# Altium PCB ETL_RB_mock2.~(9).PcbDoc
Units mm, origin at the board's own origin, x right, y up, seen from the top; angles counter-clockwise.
Board outline 130.3 x 56.5 mm, 2 copper layers (Top Layer, Bottom Layer), stack 0.137 mm thick; 9 components, 186 nets, 267 pads, 123 vias.
Unrouted connection lines stored in the file: 395.
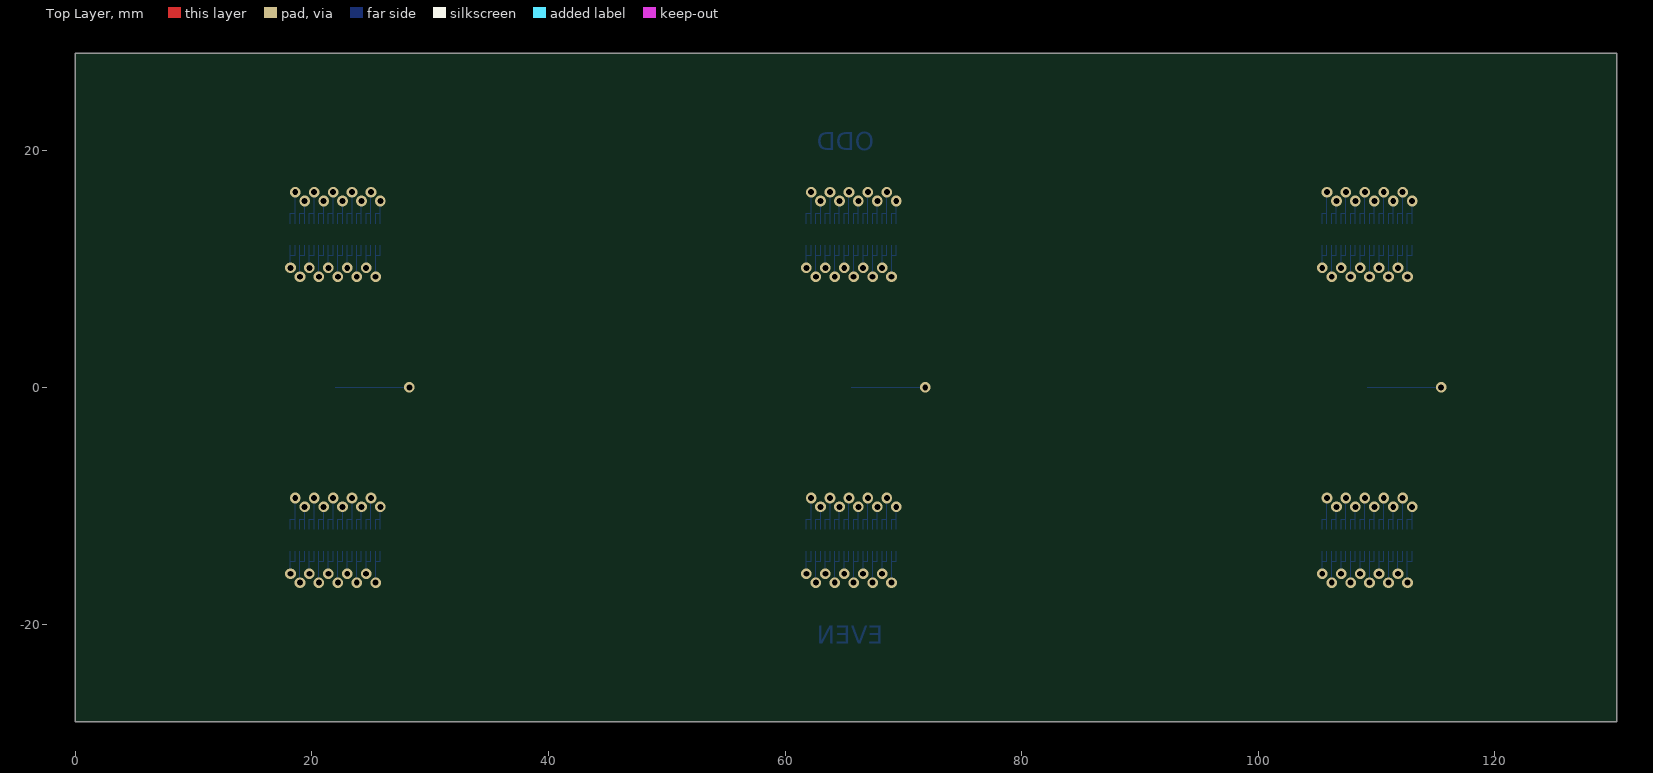
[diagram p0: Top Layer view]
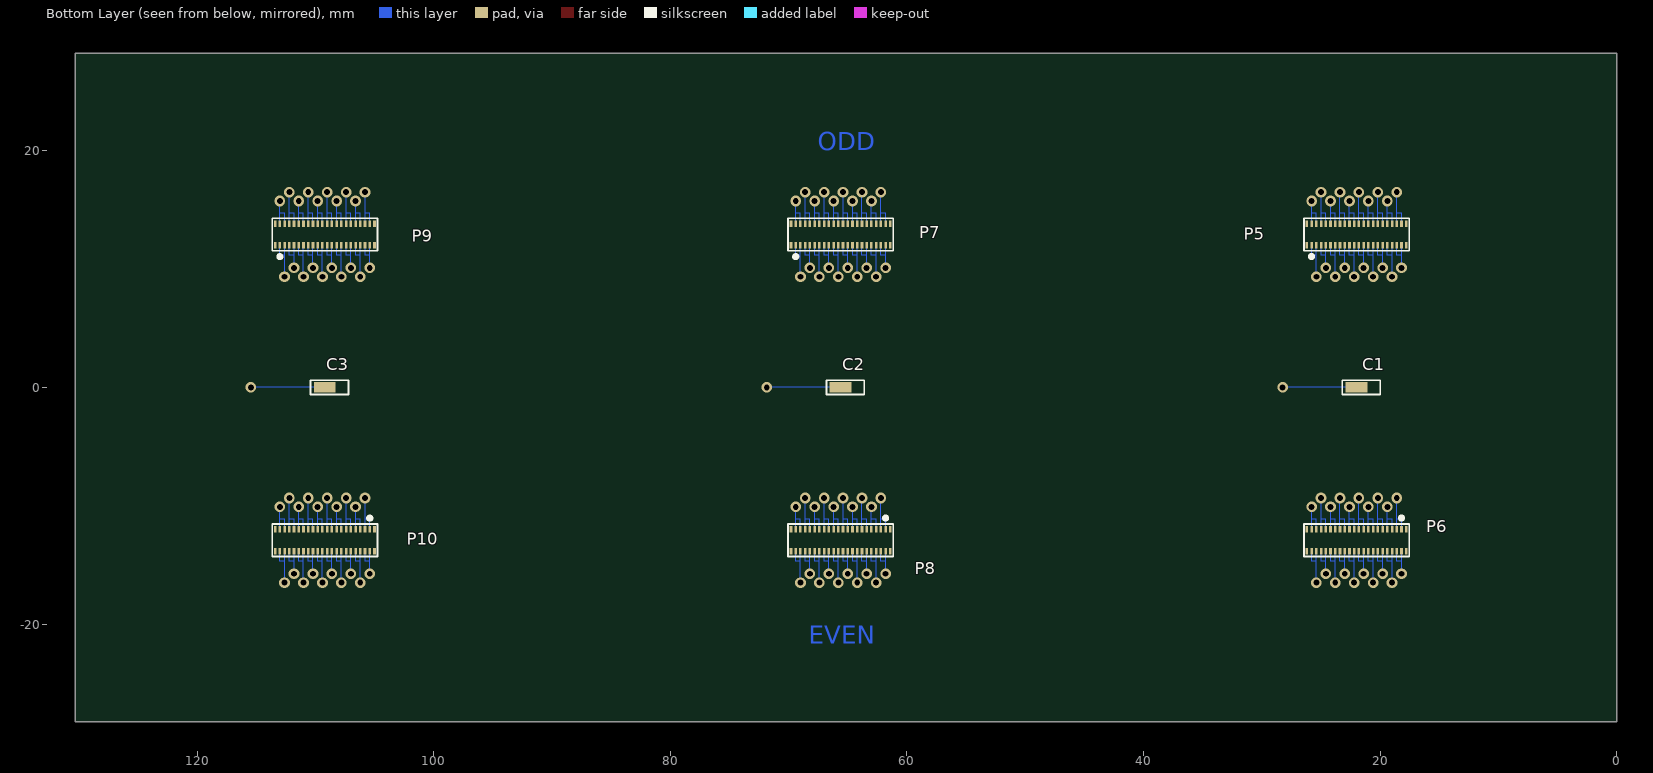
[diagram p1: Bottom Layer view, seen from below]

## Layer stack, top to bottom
Top Solder: solder mask 0.0178, Solder Resist, Dk 4.1
Top Layer: signal copper 0.0175
Dielectric 4: core 0.1016, TU-863, Dk 3.7
Bottom Layer: signal copper 0.0175
Bottom Solder: solder mask 0.0178, Solder Resist, Dk 4.1

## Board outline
0,-28.25 130.3,-28.25 130.3,28.25 0,28.25

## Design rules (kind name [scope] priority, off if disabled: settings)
Clearance [All] p1: gap=0.076 ignorepadtopadclearanceinfootprint=FALSE except(0: Arc-Hole Track-Hole SMDPad-Hole THPad-Hole Via-Hole Fill-Hole Poly-Hole Region-Hole Text-Hole)
Height [All] p1 off: minheight=0 maxheight=25.4 prefheight=12.7
HoleToHoleClearance HoleToHoleClearance_1 [InNet('GND') or InNet('LV_RB') or InNet('1V5A') or InNet('1V5D') or InNet('1V2A') or InNet('1V2B') or InNet('1V2C') or InNet('1V2D') vs InNet('GND') or InNet('LV_RB') or InNet('1V5A') or InNet('1V5D') or InNet('1V2A') or InNet('1V2B') or InNet('1V2C') or InNet('1V2D')] p1: gap=0.15 allowstackedmicrovias=TRUE
HoleToHoleClearance [All] p2: gap=0.254 allowstackedmicrovias=TRUE
MinimumSolderMaskSliver [All] p1: minsoldermaskwidth=0.102
PlaneClearance PlaneClearance_1 [InNetClass('BV')] p1: clearance=0.508
PlaneClearance [All] p2: clearance=0.152
PlaneConnect PlaneConnect_1 [All] p1: planeconnectstyle=Direct reliefexpansion=0.508 reliefentries=4 reliefconductorwidth=0.254 reliefairgap=0.254
PolygonConnect [All] p1: connectstyle=Relief reliefconductorwidth=0.254 reliefentries=4 polygonreliefangle="90 Angle" airgapwidth=0.254
RoomDefinition WP7B [InComponentClass('WP7B')] p1 off: confinementstyle=ConfineIn formatcopy=TRUE lockcomponents=FALSE outline 192.75,16.8 613.75,16.8 613.75,46.8 192.75,46.8
RoomDefinition lpGBT [InComponentClass('lpGBT')] p2 off: confinementstyle=ConfineIn formatcopy=TRUE lockcomponents=FALSE outline 192,-36.75 1047,-36.75 1047,-1.75 192,-1.75
RoutingVias [All] p1: holewidth=0.25 width=0.4 viastyle="Through Hole" minholewidth=0.15 minwidth=0.25 maxholewidth=0.711 maxwidth=1.27
SilkToSilkClearance [All] p1: silktosilkclearance=0.025
SilkToSolderMaskClearance [IsPad] p1: minsilkscreentomaskgap=0.025 clearancetoexposedcopper=TRUE
SolderMaskExpansion SolderMaskExpansion_1 [InPadClass('WP7B40PAD')] p1: expansion=0.038 istentingtop=FALSE
SolderMaskExpansion [All] p2: expansion=0.051 istentingtop=FALSE
Width Width_HS [InNetClass('HS')] p1: maxlimit=0.13 minlimit=0.076 preferedwidth=0.12 bottomlayer_minwidth=0.12 bottomlayer_maxwidth=0.12 minimp=50.000000 maximp=50.000000 favimp=50.000000 // impedance controlled signals
Width [All] p2: maxlimit=2.54 minlimit=0.076 preferedwidth=0.12 toplayer_minwidth=0.076 minimp=50.000000 maximp=50.000000 favimp=50.000000
23 further rules are at their usual default settings.

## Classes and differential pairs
pad class WP7B40PAD: P5-1 P5-2 P5-3 P5-4 P5-5 P5-6 P5-7 P5-8 P5-9 P5-10 P5-11 P5-12 P5-13 P5-14 P5-15 P5-16 P5-17 P5-18 P5-19 P5-20 P5-21 P5-22 P5-23 P5-24 P5-25 P5-26 P5-27 P5-28 P5-29 P5-30 P5-31 P5-32 P5-33 P5-34 P5-35 P5-36 P5-37 P5-38 P5-39 P5-40 P5-41 P5-42 P5-43 P5-44 P6-1 P6-2 P6-3 P6-4 P6-5 P6-6 P6-7 P6-8 P6-9 P6-10 P6-11 P6-12 P6-13 P6-14 P6-15 P6-16 P6-17 P6-18 P6-19 P6-20 P6-21 P6-22 P6-23 P6-24 P6-25 P6-26 P6-27 P6-28 P6-29 P6-30 P6-31 P6-32 P6-33 P6-34 P6-35 P6-36 P6-37 P6-38 P6-39 P6-40 P6-41 P6-42 P6-43 P6-44 P7-1 P7-2 P7-3 P7-4 P7-5 P7-6 P7-7 P7-8 P7-9 P7-10 P7-11 P7-12 P7-13 P7-14 P7-15 P7-16 P7-17 P7-18 P7-19 P7-20 P7-21 P7-22 P7-23 P7-24 P7-25 P7-26 P7-27 P7-28 P7-29 P7-30 P7-31 P7-32 P7-33 P7-34 P7-35 P7-36 P7-37 P7-38 P7-39 P7-40 P7-41 P7-42 P7-43 P7-44 P8-1 P8-2 P8-3 P8-4 P8-5 P8-6 P8-7 P8-8 P8-9 P8-10 P8-11 P8-12 P8-13 P8-14 P8-15 P8-16 P8-17 P8-18 P8-19 P8-20 P8-21 P8-22 P8-23 P8-24 P8-25 P8-26 P8-27 P8-28 P8-29 P8-30 P8-31 P8-32 P8-33 P8-34 P8-35 P8-36 P8-37 P8-38 P8-39 P8-40 P8-41 P8-42 P8-43 P8-44 P9-1 P9-2 P9-3 P9-4 P9-5 P9-6 P9-7 P9-8 P9-9 P9-10 P9-11 P9-12 P9-13 P9-14 P9-15 P9-16 P9-17 P9-18 P9-19 P9-20 P9-21 P9-22 P9-23 P9-24 P9-25 P9-26 P9-27 P9-28 P9-29 P9-30 P9-31 P9-32 P9-33 P9-34 P9-35 P9-36 P9-37 P9-38 P9-39 P9-40 P9-41 P9-42 P9-43 P9-44 P10-1 P10-2 P10-3 P10-4 P10-5 P10-6 P10-7 P10-8 P10-9 P10-10 P10-11 P10-12 P10-13 P10-14 P10-15 P10-16 P10-17 P10-18 P10-19 P10-20 P10-21 P10-22 P10-23 P10-24 P10-25 P10-26 P10-27 P10-28 P10-29 P10-30 P10-31 P10-32 P10-33 P10-34 P10-35 P10-36 P10-37 P10-38 P10-39 P10-40 P10-41 P10-42 P10-43 P10-44
component class WP7B40: P5 P6 P7 P8 P9 P10
component class WP7B: P5 P6 P7 P8 P9 P10

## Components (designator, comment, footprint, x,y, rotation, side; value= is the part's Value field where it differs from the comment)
C1 "Comment" CONTACT 22,0 r0 bottom locked
C2 "Comment" CONTACT 65.6,0 r0 bottom locked
C3 "Comment" CONTACT 109.2,0 r0 bottom locked
P5 "WP7B-P040VA1" WP7B-40P 25.8,12 r180 bottom locked
P6 "WP7B-P040VA1" WP7B-40P 18.2,-12 r0 bottom locked
P7 "WP7B-P040VA1" WP7B-40P 69.4,12 r180 bottom locked
P8 "WP7B-P040VA1" WP7B-40P 61.8,-12 r0 bottom locked
P9 "WP7B-P040VA1" WP7B-40P 113,12 r180 bottom locked
P10 "WP7B-P040VA1" WP7B-40P 105.4,-12 r0 bottom locked

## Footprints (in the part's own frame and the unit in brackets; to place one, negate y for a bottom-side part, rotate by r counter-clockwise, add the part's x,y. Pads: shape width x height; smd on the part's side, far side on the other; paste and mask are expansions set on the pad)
CONTACT [mm]
  rect 1.85x0.9 smd: 1(0,0)
  silkscreen extent -2,-0.6 1.2,0.6, body extent -1.92,-0.5 1.34,0.5, height 1.24
WP7B-40P [mm]
  rect 0.22x0.55 smd: 1(0,0) 2(0.4,0) 3(0.8,0) 4(1.2,0) 5(1.6,0) 6(2,0) 7(2.4,0) 8(2.8,0) 9(3.2,0) 10(3.6,0) 11(4,0) 12(4.4,0) 13(4.8,0) 14(5.2,0) 15(5.6,0) 16(6,0) 17(6.4,0) 18(6.8,0) 19(7.2,0) 20(7.6,0) 21(7.6,1.85) 22(7.2,1.85) 23(6.8,1.85) 24(6.4,1.85) 25(6,1.85) 26(5.6,1.85) 27(5.2,1.85) 28(4.8,1.85) 29(4.4,1.85) 30(4,1.85) 31(3.6,1.85) 32(3.2,1.85) 33(2.8,1.85) 34(2.4,1.85) 35(2,1.85) 36(1.6,1.85) 37(1.2,1.85) 38(0.8,1.85) 39(0.4,1.85) 40(0,1.85) 41(-0.4,0) 42(8,0) 43(8,1.85) 44(-0.4,1.85)
  silkscreen extent -0.65,-1 8.25,2.3, body extent -1.5,-0.32 9.1,2.17, height 0.5

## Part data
P5 P6 P7 P8 P9 P10: library part WP7B-40P, "plug"

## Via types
v1: diameter 0.9, hole 0.5, Top Layer to Bottom Layer, 123 vias

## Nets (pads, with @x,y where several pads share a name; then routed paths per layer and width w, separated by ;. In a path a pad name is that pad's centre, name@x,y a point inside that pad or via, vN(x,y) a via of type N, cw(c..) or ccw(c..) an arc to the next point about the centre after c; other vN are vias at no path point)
1V0A: 
1V2_mon0: 
1V2_mon1: 
1V2_mon2: 
1V2_mon3: 
1V2_mon4: 
1V2_mon5: 
1V2_RB: 
1V2A: 
1V2B: 
1V2C: 
1V2D: 
1V5A: 
1V5D: 
2V5F: 
2V5RX: 
2V5TX: 
ADC1: 
ADC2: 
ADC3: 
ADC4: 
ADC6: 
ADC7: 
ADC_IN18: 
ADC_IN21: 
ADC_IN22: 
ADC_IN23: 
ADC_IN24: 
ADC_IN25: 
ADC_IN28: 
ADC_IN29: 
ADC_IN30: 
AGND0: 
AGND1: 
AGND2: 
BV0: 
BV1: 
BV2: 
ECLK0N: 
ECLK0P: 
ECLK1N: 
ECLK1P: 
ECLK2N: 
ECLK2P: 
ECLK3N: 
ECLK3P: 
ECLK4N: 
ECLK4P: 
ECLK5N: 
ECLK5P: 
ECLK22N: 
ECLK22P: 
ECLK23N: 
ECLK23P: 
ECLK24N: 
ECLK24P: 
ECLK25N: 
ECLK25P: 
ECLK26N: 
ECLK26P: 
ECLK27N: 
ECLK27P: 
EDIN00N: 
EDIN00P: 
EDIN02N: 
EDIN02P: 
EDIN10N: 
EDIN10P: 
EDIN12N: 
EDIN12P: 
EDIN20N: 
EDIN20P: 
EDIN22N: 
EDIN22P: 
EDIN30N: 
EDIN30P: 
EDIN32N: 
EDIN32P: 
EDIN40N: 
EDIN40P: 
EDIN42N: 
EDIN42P: 
EDIN50N: 
EDIN50P: 
EDIN52N: 
EDIN52P: 
EDOUT00N: 
EDOUT00P: 
EDOUT02N: 
EDOUT02P: 
EDOUT10N: 
EDOUT10P: 
EDOUT20N: 
EDOUT20P: 
EDOUT22N: 
EDOUT22P: 
EDOUT30N: 
EDOUT30P: 
GBT_RESET_B: 
GND: 
I_1V5: 
I_2V5RX: 
I_2V5TX: 
IC1_SCL: 
IC1_SDA: 
LD_DIS: 
LD_RSTN: 
LV_RB: 
M1SCL: 
M1SDA: 
M2SCL: 
M2SDA: 
NetC107_1: 
NetC108_1: 
NetC155_1: 
NetC169_1: 
NetD1_1: 
NetD1_2: 
NetIC1_A2: 
NetIC1_G1: 
NetIC1_H1: 
NetIC1_L1: 
NetIC1_M1: 
NetIC1_P2: 
NetIC1_P3: 
NetIC1_R16: 
NetIC1_R17: 
NetIC1_T16: 
NetIC1_T17: 
NetIC1_U16: 
NetIC1_U17: 
NetIC2_19: 
NetIC2_21: 
NetIC5_4: 
NetIC5_5: 
NetIC6_4: 
NetIC7_4: 
NetP4_1: 
NetP8_11: 
NetP16_1: 
NetP17_1: 
NetQ1_2: 
NetR222_2: 
NetR224_2: 
NetR226_2: 
ON0: 
ON1: 
ON2: 
ON3: 
PG0: 
PG1: 
PG2: 
PG3: 
READY0: 
REFCLKN: 
REFCLKP: 
RSSI: 
RSTB0: 
RSTB1: 
RSTB2: 
SC_I2C: 
T_EDIN00N: 
T_EDIN00P: 
T_EDIN02N: 
T_EDIN02P: 
T_EDIN10N: 
T_EDIN10P: 
T_EDIN12N: 
T_EDIN12P: 
T_EDIN20N: 
T_EDIN20P: 
T_EDIN22N: 
T_EDIN22P: 
T_EDIN30N: 
T_EDIN30P: 
T_EDIN32N: 
T_EDIN32P: 
T_EDIN40N: 
T_EDIN40P: 
T_EDIN42N: 
T_EDIN42P: 
T_EDIN50N: 
T_EDIN50P: 
T_EDIN52N: 
T_EDIN52P: 
Vref: 
pads on no net: C1.1 C2.1 C3.1 P5.1 P5.2 P5.3 P5.4 P5.5 P5.6 P5.7 P5.8 P5.9 P5.10 P5.11 P5.12 P5.13 P5.14 P5.15 P5.16 P5.17 P5.18 P5.19 P5.20 P5.21 P5.22 P5.23 P5.24 P5.25 P5.26 P5.27 P5.28 P5.29 P5.30 P5.31 P5.32 P5.33 P5.34 P5.35 P5.36 P5.37 P5.38 P5.39 P5.40 P5.41 P5.42 P5.43 P5.44 P6.1 P6.2 P6.3 P6.4 P6.5 P6.6 P6.7 P6.8 P6.9 P6.10 P6.11 P6.12 P6.13 P6.14 P6.15 P6.16 P6.17 P6.18 P6.19 P6.20 P6.21 P6.22 P6.23 P6.24 P6.25 P6.26 P6.27 P6.28 P6.29 P6.30 P6.31 P6.32 P6.33 P6.34 P6.35 P6.36 P6.37 P6.38 P6.39 P6.40 P6.41 P6.42 P6.43 P6.44 P7.1 P7.2 P7.3 P7.4 P7.5 P7.6 P7.7 P7.8 P7.9 P7.10 P7.11 P7.12 P7.13 P7.14 P7.15 P7.16 P7.17 P7.18 P7.19 P7.20 P7.21 P7.22 P7.23 P7.24 P7.25 P7.26 P7.27 P7.28 P7.29 P7.30 P7.31 P7.32 P7.33 P7.34 P7.35 P7.36 P7.37 P7.38 P7.39 P7.40 P7.41 P7.42 P7.43 P7.44 P8.1 P8.2 P8.3 P8.4 P8.5 P8.6 P8.7 P8.8 P8.9 P8.10 P8.11 P8.12 P8.13 P8.14 P8.15 P8.16 P8.17 P8.18 P8.19 P8.20 P8.21 P8.22 P8.23 P8.24 P8.25 P8.26 P8.27 P8.28 P8.29 P8.30 P8.31 P8.32 P8.33 P8.34 P8.35 P8.36 P8.37 P8.38 P8.39 P8.40 P8.41 P8.42 P8.43 P8.44 P9.1 P9.2 P9.3 P9.4 P9.5 P9.6 P9.7 P9.8 P9.9 P9.10 P9.11 P9.12 P9.13 P9.14 P9.15 P9.16 P9.17 P9.18 P9.19 P9.20 P9.21 P9.22 P9.23 P9.24 P9.25 P9.26 P9.27 P9.28 P9.29 P9.30 P9.31 P9.32 P9.33 P9.34 P9.35 P9.36 P9.37 P9.38 P9.39 P9.40 P9.41 P9.42 P9.43 P9.44 P10.1 P10.2 P10.3 P10.4 P10.5 P10.6 P10.7 P10.8 P10.9 P10.10 P10.11 P10.12 P10.13 P10.14 P10.15 P10.16 P10.17 P10.18 P10.19 P10.20 P10.21 P10.22 P10.23 P10.24 P10.25 P10.26 P10.27 P10.28 P10.29 P10.30 P10.31 P10.32 P10.33 P10.34 P10.35 P10.36 P10.37 P10.38 P10.39 P10.40 P10.41 P10.42 P10.43 P10.44
copper on no net: | length 441.8
  Bottom Layer w0.102: v1(18.2,-15.75) 18.2,-14.7 ; 18.2,-13.85 18.2,-14.7 ; 18.2,-12 18.2,-11.15 18.6,-11.15 ; v1(18.2,10.1) 18.2,11.15 ; 18.2,12 18.2,11.15 ; 18.2,13.85 18.2,14.7 18.6,14.7 ; 18.6,-13.85 18.6,-14.7 18.2,-14.7 ; 18.6,-12 18.6,-11.15 ; v1(18.6,-9.35) 18.6,-11.15 ; 18.6,12 18.6,11.15 18.2,11.15 ; 18.6,13.85 18.6,14.7 ; v1(18.6,16.5) 18.6,14.7 ; v1(19,-16.5) 19,-14.7 ; 19,-13.85 19,-14.7 ; 19,-12 19,-11.15 19.4,-11.15 ; v1(19,9.35) 19,11.15 ; 19,12 19,11.15 ; 19,13.85 19,14.7 19.4,14.7 ; 19.4,-13.85 19.4,-14.7 19,-14.7 ; 19.4,-12 19.4,-11.15 ; v1(19.4,-10.1) 19.4,-11.15 ; 19.4,12 19.4,11.15 19,11.15 ; 19.4,13.85 19.4,14.7 ; v1(19.4,15.75) 19.4,14.7 ; v1(19.8,-15.75) 19.8,-14.7 ; 19.8,-13.85 19.8,-14.7 ; 19.8,-12 19.8,-11.15 20.2,-11.15 ; v1(19.8,10.1) 19.8,11.15 ; 19.8,12 19.8,11.15 ; 19.8,13.85 19.8,14.7 20.2,14.7 ; 20.2,-13.85 20.2,-14.7 19.8,-14.7 ; 20.2,-12 20.2,-11.15 ; v1(20.2,-9.35) 20.2,-11.15 ; 20.2,12 20.2,11.15 19.8,11.15 ; 20.2,13.85 20.2,14.7 ; v1(20.2,16.5) 20.2,14.7 ; v1(20.6,-16.5) 20.6,-14.7 ; 20.6,-13.85 20.6,-14.7 ; 20.6,-12 20.6,-11.15 21,-11.15 ; v1(20.6,9.35) 20.6,11.15 ; 20.6,12 20.6,11.15 ; 20.6,13.85 20.6,14.7 21,14.7 ; 21,-13.85 21,-14.7 20.6,-14.7 ; 21,-12 21,-11.15 ; v1(21,-10.1) 21,-11.15 ; 21,12 21,11.15 20.6,11.15 ; 21,13.85 21,14.7 ; v1(21,15.75) 21,14.7 ; v1(21.4,-15.75) 21.4,-14.7 ; 21.4,-13.85 21.4,-14.7 ; 21.4,-12 21.4,-11.15 21.8,-11.15 ; v1(21.4,10.1) 21.4,11.15 ; 21.4,12 21.4,11.15 ; 21.4,13.85 21.4,14.7 21.8,14.7 ; 21.8,-13.85 21.8,-14.7 21.4,-14.7 ; 21.8,-12 21.8,-11.15 ; v1(21.8,-9.35) 21.8,-11.15 ; 21.8,12 21.8,11.15 21.4,11.15 ; 21.8,13.85 21.8,14.7 ; v1(21.8,16.5) 21.8,14.7 ; 22,0 v1(28.25,0) ; v1(22.2,-16.5) 22.2,-14.7 ; 22.2,-13.85 22.2,-14.7 ; 22.2,-12 22.2,-11.15 22.6,-11.15 ; v1(22.2,9.35) 22.2,11.15 ; 22.2,12 22.2,11.15 ; 22.2,13.85 22.2,14.7 22.6,14.7 ; 22.6,-13.85 22.6,-14.7 22.2,-14.7 ; 22.6,-12 22.6,-11.15 ; v1(22.6,-10.1) 22.6,-11.15 ; 22.6,12 22.6,11.15 22.2,11.15 ; 22.6,13.85 22.6,14.7 ; v1(22.6,15.75) 22.6,14.7 ; v1(23,-15.75) 23,-14.7 ; 23,-13.85 23,-14.7 ; 23,-12 23,-11.15 23.4,-11.15 ; v1(23,10.1) 23,11.15 ; 23,12 23,11.15 ; 23,13.85 23,14.7 23.4,14.7 ; 23.4,-13.85 23.4,-14.7 23,-14.7 ; 23.4,-12 23.4,-11.15 ; v1(23.4,-9.35) 23.4,-11.15 ; 23.4,12 23.4,11.15 23,11.15 ; 23.4,13.85 23.4,14.7 ; v1(23.4,16.5) 23.4,14.7 ; v1(23.8,-16.5) 23.8,-14.7 ; 23.8,-13.85 23.8,-14.7 ; 23.8,-12 23.8,-11.15 24.2,-11.15 ; v1(23.8,9.35) 23.8,11.15 ; 23.8,12 23.8,11.15 ; 23.8,13.85 23.8,14.7 24.2,14.7 ; 24.2,-13.85 24.2,-14.7 23.8,-14.7 ; 24.2,-12 24.2,-11.15 ; v1(24.2,-10.1) 24.2,-11.15 ; 24.2,12 24.2,11.15 23.8,11.15 ; 24.2,13.85 24.2,14.7 ; v1(24.2,15.75) 24.2,14.7 ; v1(24.6,-15.75) 24.6,-14.7 ; 24.6,-13.85 24.6,-14.7 ; 24.6,-12 24.6,-11.15 25,-11.15 ; v1(24.6,10.1) 24.6,11.15 ; 24.6,12 24.6,11.15 ; 24.6,13.85 24.6,14.7 25,14.7 ; 25,-13.85 25,-14.7 24.6,-14.7 ; 25,-12 25,-11.15 ; v1(25,-9.35) 25,-11.15 ; 25,12 25,11.15 24.6,11.15 ; 25,13.85 25,14.7 ; v1(25,16.5) 25,14.7 ; v1(25.4,-16.5) 25.4,-14.7 ; 25.4,-13.85 25.4,-14.7 ; 25.4,-12 25.4,-11.15 25.8,-11.15 ; v1(25.4,9.35) 25.4,11.15 ; 25.4,12 25.4,11.15 ; 25.4,13.85 25.4,14.7 25.8,14.7 ; 25.8,-13.85 25.8,-14.7 25.4,-14.7 ; 25.8,-12 25.8,-11.15 ; v1(25.8,-10.1) 25.8,-11.15 ; 25.8,12 25.8,11.15 25.4,11.15 ; 25.8,13.85 25.8,14.7 ; v1(25.8,15.75) 25.8,14.7 ; v1(61.8,-15.75) 61.8,-14.7 ; 61.8,-13.85 61.8,-14.7 ; 61.8,-12 61.8,-11.15 62.2,-11.15 ; v1(61.8,10.1) 61.8,11.15 ; 61.8,12 61.8,11.15 ; 61.8,13.85 61.8,14.7 62.2,14.7 ; 62.2,-13.85 62.2,-14.7 61.8,-14.7 ; 62.2,-12 62.2,-11.15 ; v1(62.2,-9.35) 62.2,-11.15 ; 62.2,12 62.2,11.15 61.8,11.15 ; 62.2,13.85 62.2,14.7 ; v1(62.2,16.5) 62.2,14.7 ; v1(62.6,-16.5) 62.6,-14.7 ; 62.6,-13.85 62.6,-14.7 ; 62.6,-12 62.6,-11.15 63,-11.15 ; v1(62.6,9.35) 62.6,11.15 ; 62.6,12 62.6,11.15 ; 62.6,13.85 62.6,14.7 63,14.7 ; 63,-13.85 63,-14.7 62.6,-14.7 ; 63,-12 63,-11.15 ; v1(63,-10.1) 63,-11.15 ; 63,12 63,11.15 62.6,11.15 ; 63,13.85 63,14.7 ; v1(63,15.75) 63,14.7 ; v1(63.4,-15.75) 63.4,-14.7 ; 63.4,-13.85 63.4,-14.7 ; 63.4,-12 63.4,-11.15 63.8,-11.15 ; v1(63.4,10.1) 63.4,11.15 ; 63.4,12 63.4,11.15 ; 63.4,13.85 63.4,14.7 63.8,14.7 ; 63.8,-13.85 63.8,-14.7 63.4,-14.7 ; 63.8,-12 63.8,-11.15 ; v1(63.8,-9.35) 63.8,-11.15 ; 63.8,12 63.8,11.15 63.4,11.15 ; 63.8,13.85 63.8,14.7 ; v1(63.8,16.5) 63.8,14.7 ; v1(64.2,-16.5) 64.2,-14.7 ; 64.2,-13.85 64.2,-14.7 ; 64.2,-12 64.2,-11.15 64.6,-11.15 ; v1(64.2,9.35) 64.2,11.15 ; 64.2,12 64.2,11.15 ; 64.2,13.85 64.2,14.7 64.6,14.7 ; 64.6,-13.85 64.6,-14.7 64.2,-14.7 ; 64.6,-12 64.6,-11.15 ; v1(64.6,-10.1) 64.6,-11.15 ; 64.6,12 64.6,11.15 64.2,11.15 ; 64.6,13.85 64.6,14.7 ; v1(64.6,15.75) 64.6,14.7 ; v1(65,-15.75) 65,-14.7 ; 65,-13.85 65,-14.7 ; 65,-12 65,-11.15 65.4,-11.15 ; v1(65,10.1) 65,11.15 ; 65,12 65,11.15 ; 65,13.85 65,14.7 65.4,14.7 ; 65.4,-13.85 65.4,-14.7 65,-14.7 ; 65.4,-12 65.4,-11.15 ; v1(65.4,-9.35) 65.4,-11.15 ; 65.4,12 65.4,11.15 65,11.15 ; 65.4,13.85 65.4,14.7 ; v1(65.4,16.5) 65.4,14.7 ; 65.6,0 v1(71.85,0) ; v1(65.8,-16.5) 65.8,-14.7 ; 65.8,-13.85 65.8,-14.7 ; 65.8,-12 65.8,-11.15 66.2,-11.15 ; v1(65.8,9.35) 65.8,11.15 ; 65.8,12 65.8,11.15 ; 65.8,13.85 65.8,14.7 66.2,14.7 ; 66.2,-13.85 66.2,-14.7 65.8,-14.7 ; 66.2,-12 66.2,-11.15 ; v1(66.2,-10.1) 66.2,-11.15 ; 66.2,12 66.2,11.15 65.8,11.15 ; 66.2,13.85 66.2,14.7 ; v1(66.2,15.75) 66.2,14.7 ; v1(66.6,-15.75) 66.6,-14.7 ; 66.6,-13.85 66.6,-14.7 ; 66.6,-12 66.6,-11.15 67,-11.15 ; v1(66.6,10.1) 66.6,11.15 ; 66.6,12 66.6,11.15 ; 66.6,13.85 66.6,14.7 67,14.7 ; 67,-13.85 67,-14.7 66.6,-14.7 ; 67,-12 67,-11.15 ; v1(67,-9.35) 67,-11.15 ; 67,12 67,11.15 66.6,11.15 ; 67,13.85 67,14.7 ; v1(67,16.5) 67,14.7 ; v1(67.4,-16.5) 67.4,-14.7 ; 67.4,-13.85 67.4,-14.7 ; 67.4,-12 67.4,-11.15 67.8,-11.15 ; v1(67.4,9.35) 67.4,11.15 ; 67.4,12 67.4,11.15 ; 67.4,13.85 67.4,14.7 67.8,14.7 ; 67.8,-13.85 67.8,-14.7 67.4,-14.7 ; 67.8,-12 67.8,-11.15 ; v1(67.8,-10.1) 67.8,-11.15 ; 67.8,12 67.8,11.15 67.4,11.15 ; 67.8,13.85 67.8,14.7 ; v1(67.8,15.75) 67.8,14.7 ; v1(68.2,-15.75) 68.2,-14.7 ; 68.2,-13.85 68.2,-14.7 ; 68.2,-12 68.2,-11.15 68.6,-11.15 ; v1(68.2,10.1) 68.2,11.15 ; 68.2,12 68.2,11.15 ; 68.2,13.85 68.2,14.7 68.6,14.7 ; 68.6,-13.85 68.6,-14.7 68.2,-14.7 ; 68.6,-12 68.6,-11.15 ; v1(68.6,-9.35) 68.6,-11.15 ; 68.6,12 68.6,11.15 68.2,11.15 ; 68.6,13.85 68.6,14.7 ; v1(68.6,16.5) 68.6,14.7 ; v1(69,-16.5) 69,-14.7 ; 69,-13.85 69,-14.7 ; 69,-12 69,-11.15 69.4,-11.15 ; v1(69,9.35) 69,11.15 ; 69,12 69,11.15 ; 69,13.85 69,14.7 69.4,14.7 ; 69.4,-13.85 69.4,-14.7 69,-14.7 ; 69.4,-12 69.4,-11.15 ; v1(69.4,-10.1) 69.4,-11.15 ; 69.4,12 69.4,11.15 69,11.15 ; 69.4,13.85 69.4,14.7 ; v1(69.4,15.75) 69.4,14.7 ; v1(105.4,-15.75) 105.4,-14.7 ; 105.4,-13.85 105.4,-14.7 ; 105.4,-12 105.4,-11.15 105.8,-11.15 ; v1(105.4,10.1) 105.4,11.15 ; 105.4,12 105.4,11.15 ; 105.4,13.85 105.4,14.7 105.8,14.7 ; 105.8,-13.85 105.8,-14.7 105.4,-14.7 ; 105.8,-12 105.8,-11.15 ; v1(105.8,-9.35) 105.8,-11.15 ; 105.8,12 105.8,11.15 105.4,11.15 ; 105.8,13.85 105.8,14.7 ; v1(105.8,16.5) 105.8,14.7 ; v1(106.2,-16.5) 106.2,-14.7 ; 106.2,-13.85 106.2,-14.7 ; 106.2,-12 106.2,-11.15 106.6,-11.15 ; v1(106.2,9.35) 106.2,11.15 ; 106.2,12 106.2,11.15 ; 106.2,13.85 106.2,14.7 106.6,14.7 ; 106.6,-13.85 106.6,-14.7 106.2,-14.7 ; 106.6,-12 106.6,-11.15 ; v1(106.6,-10.1) 106.6,-11.15 ; 106.6,12 106.6,11.15 106.2,11.15 ; 106.6,13.85 106.6,14.7 ; v1(106.6,15.75) 106.6,14.7 ; v1(107,-15.75) 107,-14.7 ; 107,-13.85 107,-14.7 ; 107,-12 107,-11.15 107.4,-11.15 ; v1(107,10.1) 107,11.15 ; 107,12 107,11.15 ; 107,13.85 107,14.7 107.4,14.7 ; 107.4,-13.85 107.4,-14.7 107,-14.7 ; 107.4,-12 107.4,-11.15 ; v1(107.4,-9.35) 107.4,-11.15 ; 107.4,12 107.4,11.15 107,11.15 ; 107.4,13.85 107.4,14.7 ; v1(107.4,16.5) 107.4,14.7 ; v1(107.8,-16.5) 107.8,-14.7 ; 107.8,-13.85 107.8,-14.7 ; 107.8,-12 107.8,-11.15 108.2,-11.15 ; v1(107.8,9.35) 107.8,11.15 ; 107.8,12 107.8,11.15 ; 107.8,13.85 107.8,14.7 108.2,14.7 ; 108.2,-13.85 108.2,-14.7 107.8,-14.7 ; 108.2,-12 108.2,-11.15 ; v1(108.2,-10.1) 108.2,-11.15 ; 108.2,12 108.2,11.15 107.8,11.15 ; 108.2,13.85 108.2,14.7 ; v1(108.2,15.75) 108.2,14.7 ; v1(108.6,-15.75) 108.6,-14.7 ; 108.6,-13.85 108.6,-14.7 ; 108.6,-12 108.6,-11.15 109,-11.15 ; v1(108.6,10.1) 108.6,11.15 ; 108.6,12 108.6,11.15 ; 108.6,13.85 108.6,14.7 109,14.7 ; 109,-13.85 109,-14.7 108.6,-14.7 ; 109,-12 109,-11.15 ; v1(109,-9.35) 109,-11.15 ; 109,12 109,11.15 108.6,11.15 ; 109,13.85 109,14.7 ; v1(109,16.5) 109,14.7 ; 109.2,0 v1(115.45,0) ; v1(109.4,-16.5) 109.4,-14.7 ; 109.4,-13.85 109.4,-14.7 ; 109.4,-12 109.4,-11.15 109.8,-11.15 ; v1(109.4,9.35) 109.4,11.15 ; 109.4,12 109.4,11.15 ; 109.4,13.85 109.4,14.7 109.8,14.7 ; 109.8,-13.85 109.8,-14.7 109.4,-14.7 ; 109.8,-12 109.8,-11.15 ; v1(109.8,-10.1) 109.8,-11.15 ; 109.8,12 109.8,11.15 109.4,11.15 ; 109.8,13.85 109.8,14.7 ; v1(109.8,15.75) 109.8,14.7 ; v1(110.2,-15.75) 110.2,-14.7 ; 110.2,-13.85 110.2,-14.7 ; 110.2,-12 110.2,-11.15 110.6,-11.15 ; v1(110.2,10.1) 110.2,11.15 ; 110.2,12 110.2,11.15 ; 110.2,13.85 110.2,14.7 110.6,14.7 ; 110.6,-13.85 110.6,-14.7 110.2,-14.7 ; 110.6,-12 110.6,-11.15 ; v1(110.6,-9.35) 110.6,-11.15 ; 110.6,12 110.6,11.15 110.2,11.15 ; 110.6,13.85 110.6,14.7 ; v1(110.6,16.5) 110.6,14.7 ; v1(111,-16.5) 111,-14.7 ; 111,-13.85 111,-14.7 ; 111,-12 111,-11.15 111.4,-11.15 ; v1(111,9.35) 111,11.15 ; 111,12 111,11.15 ; 111,13.85 111,14.7 111.4,14.7 ; 111.4,-13.85 111.4,-14.7 111,-14.7 ; 111.4,-12 111.4,-11.15 ; v1(111.4,-10.1) 111.4,-11.15 ; 111.4,12 111.4,11.15 111,11.15 ; 111.4,13.85 111.4,14.7 ; v1(111.4,15.75) 111.4,14.7 ; v1(111.8,-15.75) 111.8,-14.7 ; 111.8,-13.85 111.8,-14.7 ; 111.8,-12 111.8,-11.15 112.2,-11.15 ; v1(111.8,10.1) 111.8,11.15 ; 111.8,12 111.8,11.15 ; 111.8,13.85 111.8,14.7 112.2,14.7 ; 112.2,-13.85 112.2,-14.7 111.8,-14.7 ; 112.2,-12 112.2,-11.15 ; v1(112.2,-9.35) 112.2,-11.15 ; 112.2,12 112.2,11.15 111.8,11.15 ; 112.2,13.85 112.2,14.7 ; v1(112.2,16.5) 112.2,14.7 ; v1(112.6,-16.5) 112.6,-14.7 ; 112.6,-13.85 112.6,-14.7 ; 112.6,-12 112.6,-11.15 113,-11.15 ; v1(112.6,9.35) 112.6,11.15 ; 112.6,12 112.6,11.15 ; 112.6,13.85 112.6,14.7 113,14.7 ; 113,-13.85 113,-14.7 112.6,-14.7 ; 113,-12 113,-11.15 ; v1(113,-10.1) 113,-11.15 ; 113,12 113,11.15 112.6,11.15 ; 113,13.85 113,14.7 ; v1(113,15.75) 113,14.7

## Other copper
Bottom Layer:
  text "ODD" at 67.546,20.054 h1.52
  text "EVEN" at 68.296,-21.646 h1.52

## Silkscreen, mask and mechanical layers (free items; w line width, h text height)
Mechanical 1:
  the board outline again, w0.15
Mechanical 14:
  lines w0.15: 5,28.25 38.35,28.25 ; 48.35,28.25 81.95,28.25 ; 125.3,28.25 0,28.25 ; 130.3,-28.2 130.3,23.25 ; 0,28.25 0,-28.25 130.3,-28.25 ; 0,28.25 0,28.25 ; 0,28.25 130.3,28.25 ; 130.3,-28.25 130.3,28.25 ; 130.3,-28.25 130.3,-28.25 ; 130.3,28.25 130.3,28.25

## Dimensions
130.3,-28.25 to 117.8,28.25 on Mechanical 14
0,28.25 to 130.3,7.4 on Mechanical 14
